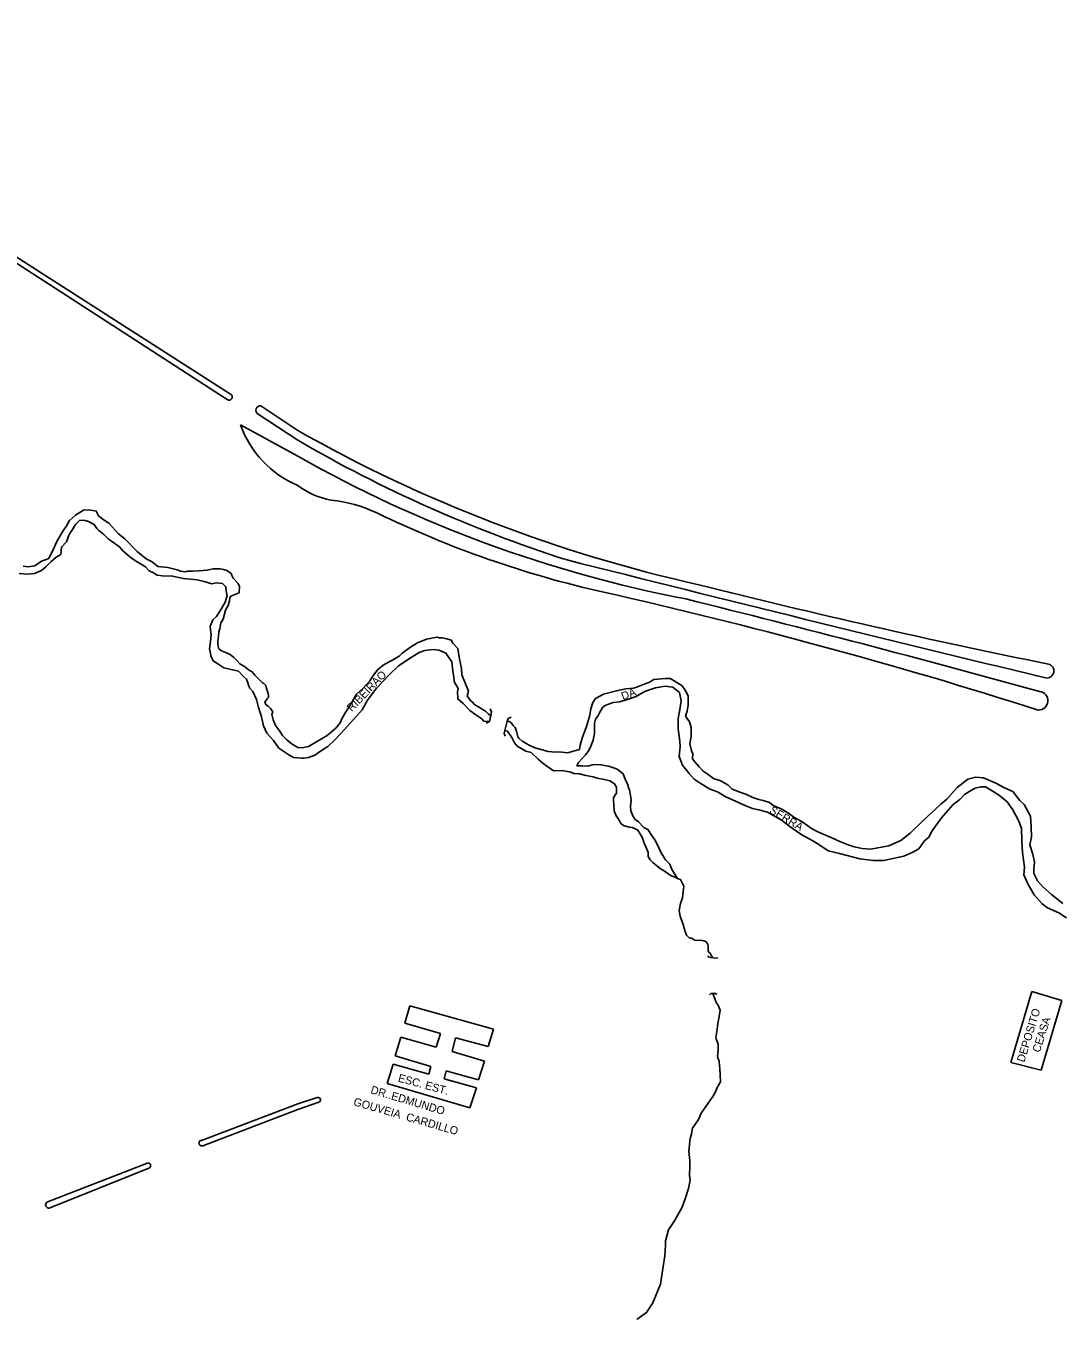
# Model space of a CAD drawing. Extents: x 325899 to 364828, y 7568995 to 7592502.
# Drawn here: x 342345 to 342864, y 7588810 to 7589457 of the extents above; entities that cross this region are included whole.
import ezdxf

# ---------------------------------------------------------------- set-up
doc = ezdxf.new("R2010")
doc.units = 0
for name, color, linetype in [('EDIFEXISTENT', 7, 'Continuous'), ('EDIFIDENTIF', 7, 'Continuous'), ('EDIFOBRAEXIS', 7, 'Continuous')]:
    doc.layers.add(name, color=color, linetype=linetype)

msp = doc.modelspace()

# ---------------------------------------------------------------- linework, layer by layer
at = {"layer": 'EDIFEXISTENT'}
for p, q in [((342577.62, 7589115.2), (342578.27, 7589113.6)), ((342578.27, 7589113.6), (342577.86, 7589111.85)), ((342577.22, 7589108.75), (342575.67, 7589107.99)), ((342577.86, 7589111.85), (342577.22, 7589108.75)), ((342584.87, 7589104.29), (342586.08, 7589109.06)), ((342586.08, 7589109.06), (342586.54, 7589110.38)), ((342586.54, 7589110.38), (342588.1, 7589110.93)), ((342584.62, 7589102.82), (342584.87, 7589104.29)), ((342585.18, 7589101.48), (342584.62, 7589102.82)), ((342686.48, 7588991.73), (342687.03, 7588991.06)), ((342687.03, 7588991.06), (342690.17, 7588990.41)), ((342690.17, 7588990.41), (342691.41, 7588990.69)), ((342687.3, 7588972.15), (342687.97, 7588972.75)), ((342687.97, 7588972.75), (342690.23, 7588972.89)), ((342690.23, 7588972.89), (342690.98, 7588972.45)), ((342838.01, 7588938.37), (342848.48, 7588973.77)), ((342848.48, 7588973.77), (342863.48, 7588969.33)), ((342534.91, 7588957.97), (342537.39, 7588966.68)), ((342537.39, 7588966.68), (342579.27, 7588954.95)), ((342863.48, 7588969.33), (342853.16, 7588934.46)), ((342552.71, 7588952.76), (342534.91, 7588957.97)), ((342530.05, 7588941.69), (342532.86, 7588951.03)), ((342532.86, 7588951.03), (342550.66, 7588945.99)), ((342550.66, 7588945.99), (342552.71, 7588952.76)), ((342560.25, 7588950.68), (342558.56, 7588943.78)), ((342576.62, 7588946.39), (342560.25, 7588950.68)), ((342579.27, 7588954.95), (342576.62, 7588946.39)), ((342526.15, 7588927.88), (342529.15, 7588937.42)), ((342529.15, 7588937.42), (342546.97, 7588932.54)), ((342547.99, 7588936.27), (342530.05, 7588941.69)), ((342558.56, 7588943.78), (342574.74, 7588939.04)), ((342574.74, 7588939.04), (342571.75, 7588929.61)), ((342853.16, 7588934.46), (342838.01, 7588938.37)), ((342546.97, 7588932.54), (342547.99, 7588936.27)), ((342555.54, 7588934.22), (342554.6, 7588930.23)), ((342560.23, 7588932.78), (342555.54, 7588934.22)), ((342571.75, 7588929.61), (342560.23, 7588932.78)), ((342567.47, 7588915.63), (342526.15, 7588927.88)), ((342554.6, 7588930.23), (342570.7, 7588925.64)), ((342570.7, 7588925.64), (342567.47, 7588915.63))]:
    msp.add_line(p, q, dxfattribs=at)
at = {"layer": 'EDIFOBRAEXIS'}
for points in [[(342446.11, 7589269.87), (342299.94, 7589364.31), (342199.85, 7589427.54), (342086.62, 7589501.91)], [(342092.03, 7589501.91), (342154.85, 7589460.08), (342361.94, 7589327.42), (342447.7, 7589272.56)], [(342461.57, 7589262.53), (342481.39, 7589249.43)], [(342481.39, 7589254.31), (342463, 7589266.71)], [(342481.39, 7589241.4), (342452.76, 7589257.13)], [(342342.12, 7589182.77), (342346.19, 7589182.41), (342349.83, 7589182.76), (342353.19, 7589184.35), (342355.4, 7589186.23), (342356.78, 7589187.54), (342357.84, 7589188.65), (342360.63, 7589190.94), (342362.85, 7589192.32), (342363.32, 7589195.98), (342365.75, 7589198.73), (342367.16, 7589202.26), (342368.71, 7589204.74), (342369.9, 7589206.86), (342370.5, 7589207.51), (342372.46, 7589209.44), (342375.08, 7589209.37), (342376.69, 7589208.75), (342379.56, 7589207.28), (342381, 7589205.32), (342381.85, 7589204.39), (342384.47, 7589202.26), (342386.71, 7589200), (342388.2, 7589199.02), (342392.38, 7589195.95), (342393.92, 7589194.08), (342398.21, 7589190.55), (342401.13, 7589188.68), (342405.18, 7589186.08), (342407.06, 7589184.2), (342409.3, 7589183.16), (342411.05, 7589181.93), (342413.59, 7589181.6), (342418.73, 7589181.51), (342424.31, 7589180.31), (342431.06, 7589179.6), (342434.65, 7589178.75), (342438.4, 7589177.65), (342440.61, 7589178.16), (342443.79, 7589177.74), (342445.48, 7589176.16), (342445.61, 7589174.25), (342445.77, 7589173.29), (342446.1, 7589171.69), (342445.14, 7589168.5), (342443.07, 7589165.05), (342440.8, 7589161.39), (342438.87, 7589159.63), (342437.58, 7589156.52), (342437.95, 7589153.12), (342438.06, 7589152.33), (342437.91, 7589150.22), (342437.28, 7589145.23), (342438.14, 7589141.32), (342439.16, 7589139.15), (342441.47, 7589137.57), (342444.41, 7589135.73), (342451.83, 7589133.96), (342454.25, 7589131.24), (342455.84, 7589129.94), (342456.42, 7589128.14), (342456.93, 7589126.55), (342457.4, 7589125.54), (342458.97, 7589123.85), (342460.69, 7589119.8), (342461.7, 7589115.8), (342463.18, 7589111.75), (342464.23, 7589106.6), (342465.87, 7589103.04), (342469.22, 7589099.37), (342472, 7589095.56), (342477.37, 7589091.78), (342479.23, 7589090.9), (342481.39, 7589090.7)], [(342344.01, 7589186.48), (342346.61, 7589186.18), (342349.86, 7589186.65), (342353.21, 7589188.97), (342356.91, 7589190.24), (342358.17, 7589192.82), (342359.06, 7589194.69), (342360.2, 7589197.24), (342360.95, 7589198.75), (342361.57, 7589199.98), (342362.71, 7589202.03), (342364.34, 7589204.41), (342365.59, 7589206.36), (342367.23, 7589209.27), (342370.2, 7589211.95), (342374.29, 7589214.47), (342377.13, 7589214.58), (342380.6, 7589214.01), (342381.77, 7589211.61), (342384.64, 7589209.43), (342386.92, 7589207.96), (342391.84, 7589202.7), (342394.92, 7589200.19), (342401.07, 7589193.89), (342405.64, 7589190.1), (342408.63, 7589188.69), (342411.5, 7589186.38), (342416.49, 7589185.83), (342421.16, 7589184.69), (342422.72, 7589183.92), (342425.34, 7589183.62), (342426.43, 7589183.97), (342428.79, 7589184), (342431.89, 7589184.08), (342436.03, 7589184.44), (342439.12, 7589185.19), (342442.53, 7589185.2), (342444.21, 7589184.74), (342445.95, 7589184.3), (342448.18, 7589182.6), (342448.37, 7589181.76), (342449.07, 7589180.5), (342451.46, 7589177.96), (342451.8, 7589177.33), (342452.19, 7589176.49), (342452.05, 7589173.21), (342450.38, 7589172.43), (342447.88, 7589171.46), (342447.36, 7589170.59), (342447.32, 7589169.14), (342446.64, 7589166.77), (342445.34, 7589164.46), (342444.13, 7589160), (342442.95, 7589158.13), (342442.38, 7589155.1), (342441.86, 7589153.72), (342441.71, 7589151.48), (342441.6, 7589150.19), (342441.43, 7589149.12), (342441.45, 7589147.18), (342441.91, 7589145.21), (342443.32, 7589144.18), (342445.77, 7589143.17), (342447.64, 7589142.27), (342449.44, 7589140.87), (342451.08, 7589139.11), (342452.35, 7589137.6), (342454.78, 7589136.33), (342457.34, 7589134.38), (342458.47, 7589133.81), (342459.99, 7589131.97), (342461.4, 7589130.51), (342462.66, 7589129.28), (342464, 7589128), (342464.28, 7589127.93), (342464.61, 7589127.68), (342465.41, 7589126.77), (342465.76, 7589125.36), (342466.29, 7589123.86), (342466.61, 7589122.62), (342466.69, 7589121.96), (342466.78, 7589120.84), (342466.23, 7589120.25), (342465.58, 7589119.56), (342464.93, 7589118.56), (342465.42, 7589117.24), (342466.6, 7589116.44), (342467.84, 7589115.26), (342468.87, 7589113.65), (342468.51, 7589112.37), (342469.05, 7589109.61), (342470.28, 7589106.75), (342472.37, 7589104.03), (342473.82, 7589101.83), (342475.85, 7589099.64), (342478.6, 7589097.42), (342481.39, 7589095.78)], [(342481.39, 7589095.78), (342483.65, 7589095.68), (342486.82, 7589096.24), (342496.18, 7589101.86), (342497.44, 7589103.01), (342500.4, 7589105.41), (342502.57, 7589108.2), (342503.61, 7589110.48), (342505.39, 7589113.65), (342507.99, 7589117.48), (342510.74, 7589122.47), (342513.95, 7589125.38), (342517.41, 7589129.23), (342519.29, 7589131.92), (342521.63, 7589134.94), (342524.61, 7589137.32), (342528.17, 7589139.14), (342532.05, 7589141.49), (342533.66, 7589142.96), (342537.83, 7589145.95), (342541.23, 7589148.2), (342545.73, 7589149.97), (342551.16, 7589150.94), (342552.23, 7589150.59), (342553.62, 7589150.61), (342555.93, 7589150.12), (342558.17, 7589149.51), (342559, 7589147.96), (342561.41, 7589145.31), (342562.28, 7589139.93), (342563.34, 7589135.31), (342563.49, 7589132.21), (342566.69, 7589124.06), (342566.16, 7589121.62), (342567.57, 7589119.46), (342568.56, 7589118.72), (342569.78, 7589117.25), (342575.33, 7589113.94), (342576.72, 7589112.54), (342577.86, 7589111.85)], [(342481.39, 7589090.7), (342483.4, 7589090.54), (342484.57, 7589090.45), (342486.73, 7589090.76), (342489.99, 7589092), (342493.22, 7589094.3), (342496.35, 7589096.38), (342499.98, 7589099.62), (342504.82, 7589104.76), (342513.67, 7589114.65), (342516.3, 7589119.51), (342520.8, 7589125.44), (342527.24, 7589132.34), (342531.79, 7589136.72), (342538.63, 7589141.22), (342542.11, 7589143.4), (342545.01, 7589144.28), (342549.17, 7589144.83), (342552.14, 7589144.47), (342555.51, 7589142.94), (342558.37, 7589138.72), (342558.92, 7589133.92), (342559.42, 7589131.15), (342559.6, 7589128.84), (342559.77, 7589128.54), (342561.54, 7589125.34), (342561.26, 7589123.76), (342561.41, 7589120.11), (342564.14, 7589117.77), (342567.46, 7589114.36), (342570.45, 7589112.22), (342573.44, 7589110.11), (342574.46, 7589109.01), (342577.22, 7589108.75)], [(342586.08, 7589109.06), (342587.07, 7589108.81), (342587.43, 7589108.61), (342588.21, 7589107.92), (342589.05, 7589106.8), (342590.04, 7589105.76), (342590.82, 7589104.03), (342591.5, 7589101.16), (342592, 7589100.5), (342593.63, 7589098.97), (342597.1, 7589096.96), (342599.97, 7589095.58), (342603.59, 7589094.64), (342606.69, 7589093.79), (342608.41, 7589093.59), (342613.36, 7589093.5), (342616.38, 7589093.19), (342619.08, 7589093.97), (342622.23, 7589094.85), (342622.69, 7589097.01), (342623.84, 7589100.94), (342625.8, 7589106.29), (342627.29, 7589111.34), (342627.9, 7589115.22), (342628.92, 7589118.39), (342630.32, 7589120.3), (342634.34, 7589122.47), (342640.72, 7589124.21), (342645.41, 7589125.11), (342649.3, 7589125.54), (342651.3, 7589126.12), (342654.53, 7589127.56), (342657.33, 7589128.54), (342659.51, 7589129.81), (342665.15, 7589130.4), (342667.66, 7589130.32), (342669.59, 7589129.23), (342673.54, 7589126.73), (342675.04, 7589124.54), (342676.68, 7589121.62), (342676.67, 7589116.93), (342676.13, 7589113.91), (342675.29, 7589111.5), (342677.21, 7589108.65), (342678.04, 7589105.88), (342678.19, 7589101.41), (342677.39, 7589097.66), (342678.32, 7589094.15), (342678.96, 7589092.6), (342678.82, 7589090.07), (342679.94, 7589088.57), (342682.19, 7589086.1), (342684.14, 7589084.04), (342686.65, 7589082.33), (342689.29, 7589080.4), (342693.02, 7589079.12), (342696.54, 7589076.93), (342698.57, 7589074.97), (342702.93, 7589073.36), (342705.42, 7589072.5), (342708.91, 7589070.79), (342711.91, 7589069.79), (342714.14, 7589069.3), (342717.26, 7589068.38), (342719.14, 7589066.86), (342723.04, 7589065.12), (342725.12, 7589064.03), (342727.25, 7589062.7), (342729.38, 7589061.05), (342733.06, 7589059.04), (342735.34, 7589057.41), (342738.23, 7589055.24), (342741.52, 7589053.69), (342748.45, 7589050.63), (342752.43, 7589048.79), (342756.56, 7589047.18), (342759.58, 7589046.19), (342763.62, 7589045.39), (342767.98, 7589045.03), (342771.41, 7589045.68), (342776.97, 7589046.69), (342782.92, 7589049.24), (342787.7, 7589052.91), (342793.8, 7589059.01), (342803.03, 7589067.42), (342805.91, 7589069.98), (342811.2, 7589075.88), (342816.44, 7589079.91), (342820.4, 7589081.02), (342824.33, 7589080.65), (342830.44, 7589078.03), (342834.83, 7589075.68), (342838.89, 7589073.9), (342842.41, 7589069.32), (342844.69, 7589067.31), (342847.77, 7589061.42), (342848.14, 7589055.98), (342848.36, 7589051.16), (342847.46, 7589047.12), (342849, 7589042.48), (342849.81, 7589038.54), (342849.52, 7589035.21), (342849.49, 7589032.78), (342851.31, 7589029.2), (342854.02, 7589026.14), (342858.23, 7589022.4), (342863.96, 7589017.82)], [(342671.27, 7589030.38), (342668.45, 7589034.85), (342667.37, 7589037.52), (342665.27, 7589039.7), (342663.04, 7589043.19), (342662.13, 7589045.27), (342660.26, 7589049.11), (342658.41, 7589051.88), (342656.46, 7589054.8), (342654.38, 7589055.8), (342651.78, 7589058.62), (342649.98, 7589059.92), (342648.94, 7589061.62), (342647.93, 7589064.13), (342647.83, 7589066.57), (342648.04, 7589069.49), (342647.84, 7589071.8), (342647.26, 7589074.42), (342646.84, 7589075.86), (342646.33, 7589077.69), (342645.24, 7589079.47), (342644.06, 7589082.62), (342641.19, 7589084.94), (342638.38, 7589085.91), (342636.53, 7589086.5), (342633.13, 7589087.09), (342629.5, 7589087.32), (342626.24, 7589086.49), (342623.68, 7589086.62), (342620.97, 7589086.6), (342621.7, 7589088.28), (342623.61, 7589090.25), (342625.39, 7589092.36), (342626.87, 7589094.36), (342627.86, 7589096.46), (342629.06, 7589099.41), (342629.73, 7589102.86), (342629.71, 7589104.99), (342629.82, 7589107.93), (342630.33, 7589109.91), (342631.6, 7589111.79), (342632.44, 7589113.51), (342633.92, 7589116), (342635.52, 7589117.06), (342639.15, 7589118.27), (342642.2, 7589118.7), (342646.34, 7589119.88), (342650.53, 7589121.3), (342653.13, 7589122.79), (342655.29, 7589123.95), (342660.21, 7589125.64), (342665.19, 7589126.49), (342669, 7589126.05), (342672.22, 7589123.31), (342673.12, 7589119.19), (342672.38, 7589114.9), (342671.66, 7589110.29), (342671.59, 7589105.23), (342672.47, 7589099.01), (342672.54, 7589096.27), (342672.12, 7589091.27), (342673.74, 7589086.93), (342677.11, 7589082.76), (342679.64, 7589079.91), (342682.58, 7589077.92), (342687.3, 7589075.1), (342688.39, 7589074.61), (342691.28, 7589073.59), (342695.49, 7589071.22), (342705.45, 7589066.61), (342708.75, 7589065.38), (342711.95, 7589064.71), (342716.24, 7589063.46), (342723.36, 7589059.44), (342728.07, 7589055.82), (342733.52, 7589052.1), (342738.9, 7589049.15), (342742.37, 7589046.98), (342746.58, 7589044.23), (342752.32, 7589042.9), (342762.41, 7589040.11), (342769.09, 7589039.37), (342774.44, 7589039.33), (342779.85, 7589040.54), (342784.4, 7589041.52), (342789, 7589043.49), (342791.89, 7589045.23), (342794.87, 7589049.11), (342796.96, 7589051.01), (342798.69, 7589054.18), (342803.22, 7589060.69), (342809.18, 7589067.33), (342812.53, 7589069.76), (342814.75, 7589072.25), (342817.49, 7589073.97), (342820.08, 7589075.41), (342822.95, 7589076.14), (342825.24, 7589076.11), (342827.77, 7589074.61), (342832.23, 7589071.75), (342836.11, 7589068.6), (342838.95, 7589064.58), (342841.75, 7589059.27), (342843.34, 7589055.41), (342843.48, 7589049.01), (342843.78, 7589043.35), (342844.73, 7589035.91), (342844.49, 7589032.13), (342846.43, 7589027.71), (342849.6, 7589022.12), (342853.65, 7589017.69), (342856.36, 7589015.73), (342861.89, 7589013.16), (342865.8, 7589010.64)], [(342584.87, 7589104.29), (342586.33, 7589103.91), (342588.4, 7589100.78), (342589.74, 7589098.17), (342591.18, 7589096.41), (342595.37, 7589093.99), (342598.03, 7589093.33), (342601.65, 7589089.94), (342604.11, 7589087.76), (342608.09, 7589085.06), (342609.31, 7589084.09), (342613.35, 7589084.28), (342617.23, 7589083.72), (342619.66, 7589082.88), (342622.23, 7589082.72), (342625.47, 7589081.8), (342629.05, 7589081.21), (342631.16, 7589080.42), (342634.66, 7589079.82), (342637.42, 7589079.23), (342639.83, 7589077.58), (342640.77, 7589075.95), (342640.76, 7589072.98), (342640.02, 7589071.79), (342639.85, 7589071.44), (342639.26, 7589070.63), (342639.21, 7589069.13), (342639.46, 7589067.5), (342639.68, 7589064.2), (342640.69, 7589061.71), (342641.42, 7589060.42), (342642.26, 7589059.15), (342643.02, 7589057.9), (342644.28, 7589056.88), (342647.07, 7589055.99), (342648.55, 7589055.83), (342649.81, 7589055.4), (342651.46, 7589054.51), (342653.66, 7589050.92), (342654.67, 7589048.03), (342655.56, 7589045.84), (342656.59, 7589043.38), (342656.69, 7589041.37), (342657.68, 7589039.67), (342658.87, 7589038.3), (342662.74, 7589035.22), (342663.83, 7589034.63), (342666.5, 7589032.9), (342668.14, 7589031.65), (342669.64, 7589031.17), (342671.64, 7589030.2), (342672.73, 7589029.76), (342673.19, 7589029.15), (342674.4, 7589026.44), (342674.07, 7589023.8), (342673.78, 7589020.67), (342672.79, 7589017.81), (342672.17, 7589014.26), (342672.6, 7589011.56), (342673.68, 7589008.69), (342674.06, 7589007.4), (342674.89, 7589004.38), (342675.72, 7589001.91)], [(342675.72, 7589001.91), (342677.06, 7589000.74), (342677.8, 7589000.52), (342678.31, 7589000.44), (342678.8, 7589000.2), (342679.1, 7588999.99), (342679.91, 7588999.55), (342681.27, 7588999.35), (342682.69, 7588999.41), (342684.38, 7588999.22), (342685.44, 7588998.76), (342686.38, 7588997.45), (342686.58, 7588996.51), (342686.59, 7588995.4), (342686.57, 7588994.56), (342686.69, 7588994.08), (342687.02, 7588993.49), (342687.72, 7588992.85), (342687.79, 7588992.47), (342687.94, 7588992.29), (342688.28, 7588991.68), (342688.46, 7588991.55), (342688.58, 7588991.47), (342688.56, 7588990.74)], [(342688.97, 7588972.81), (342690.08, 7588969.9), (342690.57, 7588968.4), (342691.61, 7588966.99), (342692.59, 7588964.47), (342692.12, 7588961.36), (342691.41, 7588957.9), (342691.17, 7588954.78), (342690.62, 7588951.8), (342690.48, 7588950.79), (342690.62, 7588950.1), (342691.62, 7588947.45), (342691.64, 7588944.82), (342691.25, 7588941.12), (342691.46, 7588941.02), (342691.45, 7588940.51), (342692.06, 7588939.18), (342692.2, 7588936.45), (342692.37, 7588935.43), (342692.78, 7588928.58), (342691.04, 7588925.79), (342690.35, 7588923.6), (342688.95, 7588921.41), (342683.11, 7588913.03), (342681.72, 7588909.8), (342678.72, 7588905.48), (342678.69, 7588904.83), (342678.22, 7588902.53), (342677.61, 7588900.36), (342677.44, 7588898.94), (342676.99, 7588893.8), (342677.43, 7588889.41), (342677.52, 7588886.52), (342677.33, 7588881.86), (342677.65, 7588879.5), (342676.85, 7588875.3), (342675.06, 7588870.15), (342673.56, 7588865.94), (342669.74, 7588859.15), (342666.79, 7588854.73), (342665.24, 7588849.1), (342665.28, 7588846.97), (342665.01, 7588841.71), (342664.17, 7588836.32), (342662.73, 7588827.47), (342658.93, 7588818.12), (342655.79, 7588813.3), (342651.11, 7588810.02), (342651.11, 7588810.02)], [(342481.39, 7588917.61), (342491.17, 7588920.8)], [(342491.9, 7588918.42), (342481.39, 7588914.79)], [(342481.39, 7588917.61), (342433.21, 7588899.41)], [(342433.89, 7588896.67), (342481.39, 7588914.79)], [(342355.96, 7588868.45), (342405.81, 7588887.85)], [(342406.92, 7588885.56), (342357.15, 7588865.55)]]:
    msp.add_lwpolyline(points, dxfattribs=at)
for centre, radius, start, end in [((342447.07, 7589271.11), 1.58, 232.06916, 66.55855), ((342462.73, 7589264.47), 2.26, 83.18585, 239.21532), ((342501.49, 7589274.47), 51.72, 199.58111, 247.12824), ((342839.46, 7589886.25), 726.33, 240.46358, 257.47646), ((342824.73, 7589840.11), 683.22, 239.83195, 252.15443), ((342797.36, 7589801.47), 643.05, 240.56974, 259.07626), ((342505.65, 7589259.32), 40.56, 233.26345, 259.24371), ((342490.86, 7589148.9), 70.94, 64.96186, 84.15476), ((342748.18, 7589680.87), 520.01, 244.08029, 257.35982), ((348659.11, 7613195.07), 24754.42, 255.868502, 256.440544), ((343616.01, 7592884.42), 3823.07, 255.85844, 258.54481), ((342074.69, 7586679.5), 2555.99, 72.30438, 77.35123), ((341073.19, 7582679.16), 6685.76, 74.567206, 76.13345), ((342855.97, 7589134.07), 3.51, 259.41992, 77.40014), ((342851.82, 7589119.22), 4.66, 267.41209, 83.91472), ((342491.58, 7588919.63), 1.24, 284.61113, 109.39205), ((342433.42, 7588898), 1.42, 98.58369, 289.507), ((342406.57, 7588886.8), 1.29, 286.0727, 125.84231), ((342356.95, 7588867.16), 1.62, 127.7259, 276.76054)]:
    msp.add_arc(centre, radius, start, end, dxfattribs=at)

# ---------------------------------------------------------------- texts
at = {"layer": 'EDIFIDENTIF'}
for s, rotation, p in [('RIBEIRAO', 46.24564, (342508.42, 7589113.47)), ('DA', 20.39284, (342644.03, 7589119.4)), ('SERRA', 328.78224, (342716.87, 7589063.44)), ('DEPOSITO', 72.94348, (342844.67, 7588938.19)), ('CEASA', 72.23855, (342852.4, 7588943.03)), ('ESC. EST.', 344.85122, (342531.25, 7588928.84)), ('DR..EDMUNDO', 343.33813, (342517.51, 7588923.03)), ('GOUVEIA  CARDILLO', 343.84516, (342508.95, 7588917.03))]:
    msp.add_text(s, height=4, rotation=rotation, dxfattribs=at).set_placement(p)

doc.saveas('drawing.dxf')
